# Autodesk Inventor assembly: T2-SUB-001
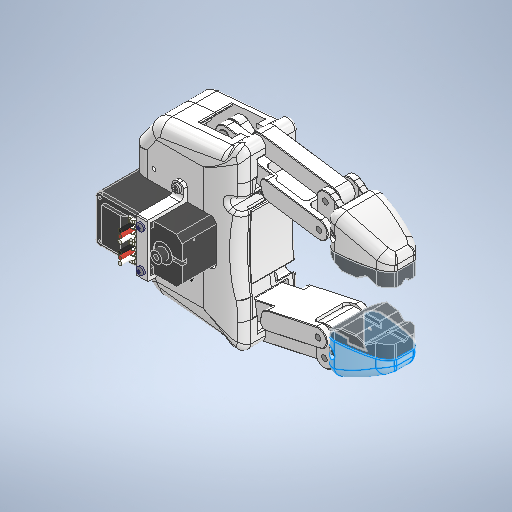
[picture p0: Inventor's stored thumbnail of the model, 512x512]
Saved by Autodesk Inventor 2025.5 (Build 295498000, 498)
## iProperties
Created: 2026-10
Part Number: T2-SUB-001
Document SubType Name: Assembly
Designer: Luis MuÃ±oz
Project: TESIS 2 - Plataforma mecatrÃ³nica preventiva desacoplada
Description: Gripper adaptativo instrumentado con puntas flexibles
Author: Luis M
Title: Gripper adaptativo instrumentado con puntas flexibles
Revision Number: 00
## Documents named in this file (22)
- C:\Users\Luis M\Desktop\TESIS\CAD_TESIS_PRUEBA_MIGRACION\GRIPPER_ADAPTATIVO_INSTRUMENTADO.iam
- C:\Users\Luis M\Desktop\TESIS\CAD_TESIS\PLACA_INFERIOR_GRIPPER.ipt
- C:\Users\Luis M\Desktop\TESIS\CAD_TESIS\ESLABON_INTERIOR.ipt
- C:\Users\Luis M\Desktop\TESIS\CAD_TESIS\ESLABON_EXTERIOR.ipt
- C:\Users\Luis M\Desktop\TESIS\CAD_TESIS\ESLABON_DISTAL.ipt
- C:\Users\Luis M\Desktop\TESIS\CAD_TESIS\CARCASA_DISTAL_DEDO.ipt
- C:\Users\Luis M\Desktop\TESIS\CAD_TESIS\SOPORTE_PUNTA_FLEXIBLE.ipt
- C:\Users\Luis M\Desktop\TESIS\CAD_TESIS\PUNTA_CONTACTO_REMOVIBLE.ipt
- C:\Users\Luis M\Desktop\TESIS\CAD_TESIS\PLACA_SUPERIOR_GRIPPER.ipt
- C:\Users\Luis M\Desktop\TESIS\CAD_TESIS\FEETECH_ST-3215-C018.iam
- C:\Users\Luis M\Desktop\TESIS\CAD_TESIS\ACOPLE_EJE_SERVOMOTOR.ipt
- C:\Users\Luis M\Desktop\TESIS\CAD_TESIS\LEVA_ACCIONAMIENTO.ipt
- C:\Users\Luis M\Desktop\TESIS\CAD_TESIS\BIELA_MOTRIZ.ipt
- C:\Users\Luis M\Desktop\TESIS\CAD_TESIS\MCM_99461A931_TORNILLO_M2_5X8.ipt
- C:\Users\Luis M\Desktop\TESIS\CAD_TESIS\INSERTO_ROSCADO_M3_D5_L5.ipt
- C:\Users\Luis M\Desktop\TESIS\CAD_TESIS\PASADOR_CILINDRICO_D3X16.ipt
- C:\Users\Luis M\Desktop\TESIS\CAD_TESIS\PASADOR_CILINDRICO_D3X24.ipt
- C:\Users\Luis M\Desktop\TESIS\CAD_TESIS\COJINETE_LISO_D3_D6_L5.ipt
- C:\Users\Luis M\Desktop\TESIS\CAD_TESIS\TORNILLO_HEX_INTERIOR_M3X10.ipt
- C:\Users\Luis M\Desktop\TESIS\CAD_TESIS\BRIDA_SERVOMOTOR.ipt
- C:\Users\Luis M\Desktop\TESIS\CAD_TESIS\TORNILLO_M2X4.ipt
- C:\Users\Luis M\Desktop\TESIS\CAD_TESIS\TORNILLO_HEX_INTERIOR_M3X6.ipt
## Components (70 placed, 21 different names)
1. PLACA_INFERIOR_GRIPPER:1
2. ESLABON_INTERIOR:1 — Coincidencia:1, Coincidencia:2, Coincidencia:12, Coincidencia:13, Coincidencia:49, Nivelación:13, Coincidencia:65, Coincidencia:66, Nivelación:15, Coincidencia:87, Coincidencia:92
3. ESLABON_INTERIOR:2 — Coincidencia:3, Coincidencia:4, Coincidencia:9, Coincidencia:14, Coincidencia:47, Nivelación:10, Coincidencia:63, Coincidencia:64, Nivelación:14, Coincidencia:89
4. ESLABON_EXTERIOR:1 — Coincidencia:6, Coincidencia:7, Coincidencia:11, Coincidencia:69
5. ESLABON_EXTERIOR:2 — Coincidencia:5, Coincidencia:8, Coincidencia:10, Coincidencia:70
6. ESLABON_DISTAL:1
7. ESLABON_DISTAL:2
8. Distal_Shell:2 — Coincidencia:15, Coincidencia:23, Nivelación:2, Nivelación:3, Coincidencia:71, Coincidencia:73, Coincidencia:74, Coincidencia:136
9. Distal_Shell:3 — Coincidencia:16, Coincidencia:24, Nivelación:1, Nivelación:4, Coincidencia:77, Coincidencia:78, Coincidencia:137
10. SOPORTE_PUNTA_FLEXIBLE:1 — Nivelación:3, Coincidencia:28, Coincidencia:136
11. SOPORTE_PUNTA_FLEXIBLE:2 — Coincidencia:29, Nivelación:4, Coincidencia:137
12. PUNTA_CONTACTO_REMOVIBLE:1 — Coincidencia:17, Coincidencia:18, Coincidencia:22, Coincidencia:23, Nivelación:2, Coincidencia:28, Coincidencia:57, Coincidencia:58, Coincidencia:59, Coincidencia:60, Coincidencia:61, Coincidencia:62, Coincidencia:72
13. PUNTA_CONTACTO_REMOVIBLE:2 — Coincidencia:19, Coincidencia:20, Coincidencia:21, Coincidencia:24, Nivelación:1, Coincidencia:29, Coincidencia:51, Coincidencia:52, Coincidencia:53, Coincidencia:54, Coincidencia:55, Coincidencia:56, Coincidencia:75, Coincidencia:76
14. PLACA_SUPERIOR_GRIPPER:1 — Coincidencia:25, Coincidencia:26, Coincidencia:27, Coincidencia:30, Coincidencia:31, Nivelación:5, Coincidencia:98, Coincidencia:99, Coincidencia:100, Coincidencia:102, Coincidencia:103, Coincidencia:104, Coincidencia:105, Coincidencia:106, Coincidencia:122, Coincidencia:123, Coincidencia:124, Coincidencia:126, Coincidencia:127, Coincidencia:130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
15. FEETECH_ST-3215-C018:1 [sub-assembly] — Coincidencia:30, Coincidencia:31, Nivelación:5, Coincidencia:35, Coincidencia:36, Coincidencia:135
16. ACOPLE_EJE:2 — Coincidencia:32, Coincidencia:33, Coincidencia:34, Coincidencia:36
17. Cam:1 — Coincidencia:32, Coincidencia:33, Coincidencia:34, Coincidencia:35, Coincidencia:45, Coincidencia:46, Nivelación:8, Nivelación:9, Coincidencia:112, Coincidencia:113, Coincidencia:114, Coincidencia:115, Coincidencia:116, Coincidencia:117, Coincidencia:118, Coincidencia:119, Coincidencia:120, Coincidencia:121, Coincidencia:135
18. BIELA_MOTRIZ:1 — Coincidencia:79, Coincidencia:80, Coincidencia:84, Nivelación:19, Coincidencia:85, Nivelación:21, Coincidencia:87
19. BIELA_MOTRIZ:2 — Coincidencia:81, Coincidencia:82, Coincidencia:83, Nivelación:18, Nivelación:20, Coincidencia:88, Coincidencia:89
20. MCM_99461A931_TORNILLO_M2_5X8:1 — Coincidencia:57, Coincidencia:61
21. INSERTO_ROSCADO_M3_D5_L5:1 — Coincidencia:85, Nivelación:21
22. PASADOR_CILINDRICO_D3X16:1 — Coincidencia:68, Nivelación:17
23. PASADOR_CILINDRICO_D3X24:1 — Coincidencia:65
24. COJINETE_LISO_D3_D6_L5:1 — Coincidencia:49, Nivelación:13, Coincidencia:79, Coincidencia:91
25. MCM_99461A931_TORNILLO_M2_5X8:2 — Coincidencia:101, Coincidencia:107
26. INSERTO_ROSCADO_M3_D5_L5:2 — Nivelación:20, Coincidencia:88
27. PASADOR_CILINDRICO_D3X16:2 — Coincidencia:69
28. PASADOR_CILINDRICO_D3X24:2 — Coincidencia:66, Nivelación:15
29. COJINETE_LISO_D3_D6_L5:2 — Coincidencia:83, Nivelación:18, Coincidencia:95, Coincidencia:96
30. MCM_99461A931_TORNILLO_M2_5X8:3 — Coincidencia:71, Coincidencia:73
31. INSERTO_ROSCADO_M3_D5_L5:3 — Coincidencia:45, Nivelación:9, Coincidencia:80
32. PASADOR_CILINDRICO_D3X16:3 — Coincidencia:67, Nivelación:16
33. PASADOR_CILINDRICO_D3X24:3 — Coincidencia:63
34. COJINETE_LISO_D3_D6_L5:3 — Coincidencia:47, Nivelación:10, Coincidencia:82, Coincidencia:90, Coincidencia:93
35. MCM_99461A931_TORNILLO_M2_5X8:4 — Coincidencia:72, Coincidencia:74
36. INSERTO_ROSCADO_M3_D5_L5:4 — Coincidencia:46, Nivelación:8, Coincidencia:81
37. PASADOR_CILINDRICO_D3X16:4 — Coincidencia:70
38. PASADOR_CILINDRICO_D3X24:4 — Coincidencia:64, Nivelación:14
39. COJINETE_LISO_D3_D6_L5:4 — Coincidencia:84, Nivelación:19, Coincidencia:94, Coincidencia:97
40. MCM_99461A931_TORNILLO_M2_5X8:5 — Coincidencia:102, Coincidencia:108
41. MCM_99461A931_TORNILLO_M2_5X8:6 — Coincidencia:104, Coincidencia:105
42. MCM_99461A931_TORNILLO_M2_5X8:7 — Coincidencia:75, Coincidencia:77
43. MCM_99461A931_TORNILLO_M2_5X8:8 — Coincidencia:76, Coincidencia:78
44. MCM_99461A931_TORNILLO_M2_5X8:10 — Coincidencia:125, Coincidencia:129
45. MCM_99461A931_TORNILLO_M2_5X8:11 — Coincidencia:122, Coincidencia:127
46. MCM_99461A931_TORNILLO_M2_5X8:12 — Coincidencia:123, Coincidencia:126
47. MCM_99461A931_TORNILLO_M2_5X8:13 — Coincidencia:51, Coincidencia:56
48. MCM_99461A931_TORNILLO_M2_5X8:14 — Coincidencia:58, Coincidencia:62
49. MCM_99461A931_TORNILLO_M2_5X8:16 — Coincidencia:124, Coincidencia:128
50. MCM_99461A931_TORNILLO_M2_5X8:17 — Coincidencia:52, Coincidencia:54
51. MCM_99461A931_TORNILLO_M2_5X8:18 — Coincidencia:53, Coincidencia:55
52. MCM_99461A931_TORNILLO_M2_5X8:19 — Coincidencia:59, Coincidencia:60
53. MCM_99461A931_TORNILLO_M2_5X8:20 — Coincidencia:103, Coincidencia:106
54. hex_socket_cylindrical_head_M3x10:1 — Coincidencia:90, Coincidencia:93
55. hex_socket_cylindrical_head_M3x10:2 — Coincidencia:91, Coincidencia:92
56. hex_socket_cylindrical_head_M3x10:3 — Coincidencia:94, Coincidencia:97
57. hex_socket_cylindrical_head_M3x10:4 — Coincidencia:95, Coincidencia:96
58. BRIDA_SERVOMOTOR:1
59. TORNILLO_M2X4:1 — Coincidencia:109, Nivelación:22
60. TORNILLO_M2X4:2 — Coincidencia:110, Nivelación:22, Coincidencia:111
61. TORNILLO_HEX_INTERIOR_M3X6:1 — Coincidencia:114, Coincidencia:120
62. TORNILLO_HEX_INTERIOR_M3X6:2 — Coincidencia:112, Coincidencia:113
63. TORNILLO_HEX_INTERIOR_M3X6:3 — Coincidencia:116, Coincidencia:119
64. TORNILLO_HEX_INTERIOR_M3X6:4 — Coincidencia:117, Coincidencia:118
65. TORNILLO_HEX_INTERIOR_M3X6:5 — Coincidencia:115, Coincidencia:121
66. INSERTO_ROSCADO_M3_D5_L5:9 — Coincidencia:131, Nivelación:27
67. INSERTO_ROSCADO_M3_D5_L5:10 — Coincidencia:130, Nivelación:23
68. INSERTO_ROSCADO_M3_D5_L5:11 — Coincidencia:134, Nivelación:26
69. INSERTO_ROSCADO_M3_D5_L5:12 — Coincidencia:132, Nivelación:24
70. INSERTO_ROSCADO_M3_D5_L5:13 — Coincidencia:133, Nivelación:25
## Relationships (149: Mate 126, Flush 23)
- Coincidencia:1 [Mate]: ESLABON_INTERIOR:1
- Coincidencia:2 [Mate]: ESLABON_INTERIOR:1
- Coincidencia:3 [Mate]: ESLABON_INTERIOR:2
- Coincidencia:4 [Mate]: ESLABON_INTERIOR:2
- Coincidencia:5 [Mate]: ESLABON_EXTERIOR:2
- Coincidencia:6 [Mate]: ESLABON_EXTERIOR:1
- Coincidencia:7 [Mate]: ESLABON_EXTERIOR:1
- Coincidencia:8 [Mate]: ESLABON_EXTERIOR:2
- Coincidencia:9 [Mate]: ESLABON_INTERIOR:2
- Coincidencia:10 [Mate]: ESLABON_EXTERIOR:2
- Coincidencia:11 [Mate]: ESLABON_EXTERIOR:1
- Coincidencia:12 [Mate]: ESLABON_INTERIOR:1
- Coincidencia:13 [Mate]: ESLABON_INTERIOR:1
- Coincidencia:14 [Mate]: ESLABON_INTERIOR:2
- Coincidencia:15 [Mate]: Distal_Shell:2
- Coincidencia:16 [Mate]: Distal_Shell:3
- Coincidencia:17 [Mate]: PUNTA_CONTACTO_REMOVIBLE:1
- Coincidencia:18 [Mate]: PUNTA_CONTACTO_REMOVIBLE:1
- Coincidencia:19 [Mate]: PUNTA_CONTACTO_REMOVIBLE:2
- Coincidencia:20 [Mate]: PUNTA_CONTACTO_REMOVIBLE:2
- Coincidencia:21 [Mate]: PUNTA_CONTACTO_REMOVIBLE:2
- Coincidencia:22 [Mate]: PUNTA_CONTACTO_REMOVIBLE:1
- Coincidencia:23 [Mate]: Distal_Shell:2 ↔ PUNTA_CONTACTO_REMOVIBLE:1
- Coincidencia:24 [Mate]: Distal_Shell:3 ↔ PUNTA_CONTACTO_REMOVIBLE:2
- Nivelación:1 [Flush]: Distal_Shell:3 ↔ PUNTA_CONTACTO_REMOVIBLE:2
- Nivelación:2 [Flush]: Distal_Shell:2 ↔ PUNTA_CONTACTO_REMOVIBLE:1
- Coincidencia:25 [Mate]: PLACA_SUPERIOR_GRIPPER:1
- Coincidencia:26 [Mate]: PLACA_SUPERIOR_GRIPPER:1
- Coincidencia:27 [Mate]: PLACA_SUPERIOR_GRIPPER:1
- Nivelación:3 [Flush]: Distal_Shell:2 ↔ SOPORTE_PUNTA_FLEXIBLE:1
- Coincidencia:28 [Mate]: SOPORTE_PUNTA_FLEXIBLE:1 ↔ PUNTA_CONTACTO_REMOVIBLE:1
- Coincidencia:29 [Mate]: SOPORTE_PUNTA_FLEXIBLE:2 ↔ PUNTA_CONTACTO_REMOVIBLE:2
- Nivelación:4 [Flush]: Distal_Shell:3 ↔ SOPORTE_PUNTA_FLEXIBLE:2
- Coincidencia:30 [Mate]: PLACA_SUPERIOR_GRIPPER:1 ↔ FEETECH_ST-3215-C018:1
- Coincidencia:31 [Mate]: PLACA_SUPERIOR_GRIPPER:1 ↔ FEETECH_ST-3215-C018:1
- Nivelación:5 [Flush]: PLACA_SUPERIOR_GRIPPER:1 ↔ FEETECH_ST-3215-C018:1
- Coincidencia:32 [Mate]: ACOPLE_EJE:2 ↔ Cam:1
- Coincidencia:33 [Mate]: ACOPLE_EJE:2 ↔ Cam:1
- Coincidencia:34 [Mate]: ACOPLE_EJE:2 ↔ Cam:1
- Coincidencia:35 [Mate]: FEETECH_ST-3215-C018:1 ↔ Cam:1
- Coincidencia:36 [Mate]: FEETECH_ST-3215-C018:1 ↔ ACOPLE_EJE:2
- Coincidencia:45 [Mate]: Cam:1 ↔ INSERTO_ROSCADO_M3_D5_L5:3
- Coincidencia:46 [Mate]: Cam:1 ↔ INSERTO_ROSCADO_M3_D5_L5:4
- Nivelación:8 [Flush]: Cam:1 ↔ INSERTO_ROSCADO_M3_D5_L5:4
- Nivelación:9 [Flush]: Cam:1 ↔ INSERTO_ROSCADO_M3_D5_L5:3
- Coincidencia:47 [Mate]: ESLABON_INTERIOR:2 ↔ COJINETE_LISO_D3_D6_L5:3
- Coincidencia:49 [Mate]: ESLABON_INTERIOR:1 ↔ COJINETE_LISO_D3_D6_L5:1
- Nivelación:10 [Flush]: ESLABON_INTERIOR:2 ↔ COJINETE_LISO_D3_D6_L5:3
- Nivelación:13 [Flush]: ESLABON_INTERIOR:1 ↔ COJINETE_LISO_D3_D6_L5:1
- Coincidencia:51 [Mate]: PUNTA_CONTACTO_REMOVIBLE:2 ↔ MCM_99461A931_TORNILLO_M2_5X8:13
- Coincidencia:52 [Mate]: PUNTA_CONTACTO_REMOVIBLE:2 ↔ MCM_99461A931_TORNILLO_M2_5X8:17
- Coincidencia:53 [Mate]: PUNTA_CONTACTO_REMOVIBLE:2 ↔ MCM_99461A931_TORNILLO_M2_5X8:18
- Coincidencia:54 [Mate]: PUNTA_CONTACTO_REMOVIBLE:2 ↔ MCM_99461A931_TORNILLO_M2_5X8:17
- Coincidencia:55 [Mate]: PUNTA_CONTACTO_REMOVIBLE:2 ↔ MCM_99461A931_TORNILLO_M2_5X8:18
- Coincidencia:56 [Mate]: PUNTA_CONTACTO_REMOVIBLE:2 ↔ MCM_99461A931_TORNILLO_M2_5X8:13
- Coincidencia:57 [Mate]: PUNTA_CONTACTO_REMOVIBLE:1 ↔ MCM_99461A931_TORNILLO_M2_5X8:1
- Coincidencia:58 [Mate]: PUNTA_CONTACTO_REMOVIBLE:1 ↔ MCM_99461A931_TORNILLO_M2_5X8:14
- Coincidencia:59 [Mate]: PUNTA_CONTACTO_REMOVIBLE:1 ↔ MCM_99461A931_TORNILLO_M2_5X8:19
- Coincidencia:60 [Mate]: PUNTA_CONTACTO_REMOVIBLE:1 ↔ MCM_99461A931_TORNILLO_M2_5X8:19
- Coincidencia:61 [Mate]: PUNTA_CONTACTO_REMOVIBLE:1 ↔ MCM_99461A931_TORNILLO_M2_5X8:1
- Coincidencia:62 [Mate]: PUNTA_CONTACTO_REMOVIBLE:1 ↔ MCM_99461A931_TORNILLO_M2_5X8:14
- Coincidencia:63 [Mate]: ESLABON_INTERIOR:2 ↔ PASADOR_CILINDRICO_D3X24:3
- Coincidencia:64 [Mate]: ESLABON_INTERIOR:2 ↔ PASADOR_CILINDRICO_D3X24:4
- Coincidencia:65 [Mate]: ESLABON_INTERIOR:1 ↔ PASADOR_CILINDRICO_D3X24:1
- Coincidencia:66 [Mate]: ESLABON_INTERIOR:1 ↔ PASADOR_CILINDRICO_D3X24:2
- Nivelación:14 [Flush]: ESLABON_INTERIOR:2 ↔ PASADOR_CILINDRICO_D3X24:4
- Nivelación:15 [Flush]: ESLABON_INTERIOR:1 ↔ PASADOR_CILINDRICO_D3X24:2
- Coincidencia:67 [Mate]: PASADOR_CILINDRICO_D3X16:3
- Coincidencia:68 [Mate]: PASADOR_CILINDRICO_D3X16:1
- Coincidencia:69 [Mate]: ESLABON_EXTERIOR:1 ↔ PASADOR_CILINDRICO_D3X16:2
- Coincidencia:70 [Mate]: ESLABON_EXTERIOR:2 ↔ PASADOR_CILINDRICO_D3X16:4
- Nivelación:16 [Flush]: PASADOR_CILINDRICO_D3X16:3
- Nivelación:17 [Flush]: PASADOR_CILINDRICO_D3X16:1
- Coincidencia:71 [Mate]: Distal_Shell:2 ↔ MCM_99461A931_TORNILLO_M2_5X8:3
- Coincidencia:72 [Mate]: PUNTA_CONTACTO_REMOVIBLE:1 ↔ MCM_99461A931_TORNILLO_M2_5X8:4
- Coincidencia:73 [Mate]: Distal_Shell:2 ↔ MCM_99461A931_TORNILLO_M2_5X8:3
- Coincidencia:74 [Mate]: Distal_Shell:2 ↔ MCM_99461A931_TORNILLO_M2_5X8:4
- Coincidencia:75 [Mate]: PUNTA_CONTACTO_REMOVIBLE:2 ↔ MCM_99461A931_TORNILLO_M2_5X8:7
- Coincidencia:76 [Mate]: PUNTA_CONTACTO_REMOVIBLE:2 ↔ MCM_99461A931_TORNILLO_M2_5X8:8
- Coincidencia:77 [Mate]: Distal_Shell:3 ↔ MCM_99461A931_TORNILLO_M2_5X8:7
- Coincidencia:78 [Mate]: Distal_Shell:3 ↔ MCM_99461A931_TORNILLO_M2_5X8:8
- Coincidencia:79 [Mate]: BIELA_MOTRIZ:1 ↔ COJINETE_LISO_D3_D6_L5:1
- Coincidencia:80 [Mate]: BIELA_MOTRIZ:1 ↔ INSERTO_ROSCADO_M3_D5_L5:3
- Coincidencia:81 [Mate]: BIELA_MOTRIZ:2 ↔ INSERTO_ROSCADO_M3_D5_L5:4
- Coincidencia:82 [Mate]: BIELA_MOTRIZ:2 ↔ COJINETE_LISO_D3_D6_L5:3
- Coincidencia:83 [Mate]: BIELA_MOTRIZ:2 ↔ COJINETE_LISO_D3_D6_L5:2
- Nivelación:18 [Flush]: BIELA_MOTRIZ:2 ↔ COJINETE_LISO_D3_D6_L5:2
- Coincidencia:84 [Mate]: BIELA_MOTRIZ:1 ↔ COJINETE_LISO_D3_D6_L5:4
- Nivelación:19 [Flush]: BIELA_MOTRIZ:1 ↔ COJINETE_LISO_D3_D6_L5:4
- Coincidencia:85 [Mate]: BIELA_MOTRIZ:1 ↔ INSERTO_ROSCADO_M3_D5_L5:1
- Nivelación:20 [Flush]: BIELA_MOTRIZ:2 ↔ INSERTO_ROSCADO_M3_D5_L5:2
- Nivelación:21 [Flush]: BIELA_MOTRIZ:1 ↔ INSERTO_ROSCADO_M3_D5_L5:1
- Coincidencia:87 [Mate]: ESLABON_INTERIOR:1 ↔ BIELA_MOTRIZ:1
- Coincidencia:88 [Mate]: BIELA_MOTRIZ:2 ↔ INSERTO_ROSCADO_M3_D5_L5:2
- Coincidencia:89 [Mate]: ESLABON_INTERIOR:2 ↔ BIELA_MOTRIZ:2
- Coincidencia:90 [Mate]: COJINETE_LISO_D3_D6_L5:3 ↔ hex_socket_cylindrical_head_M3x10:1
- Coincidencia:91 [Mate]: COJINETE_LISO_D3_D6_L5:1 ↔ hex_socket_cylindrical_head_M3x10:2
- Coincidencia:92 [Mate]: ESLABON_INTERIOR:1 ↔ hex_socket_cylindrical_head_M3x10:2
- Coincidencia:93 [Mate]: COJINETE_LISO_D3_D6_L5:3 ↔ hex_socket_cylindrical_head_M3x10:1
- Coincidencia:94 [Mate]: COJINETE_LISO_D3_D6_L5:4 ↔ hex_socket_cylindrical_head_M3x10:3
- Coincidencia:95 [Mate]: COJINETE_LISO_D3_D6_L5:2 ↔ hex_socket_cylindrical_head_M3x10:4
- Coincidencia:96 [Mate]: COJINETE_LISO_D3_D6_L5:2 ↔ hex_socket_cylindrical_head_M3x10:4
- Coincidencia:97 [Mate]: COJINETE_LISO_D3_D6_L5:4 ↔ hex_socket_cylindrical_head_M3x10:3
- Coincidencia:98 [Mate]: PLACA_SUPERIOR_GRIPPER:1
- Coincidencia:99 [Mate]: PLACA_SUPERIOR_GRIPPER:1
- Coincidencia:100 [Mate]: PLACA_SUPERIOR_GRIPPER:1
- Coincidencia:101 [Mate]: MCM_99461A931_TORNILLO_M2_5X8:2
- Coincidencia:102 [Mate]: PLACA_SUPERIOR_GRIPPER:1 ↔ MCM_99461A931_TORNILLO_M2_5X8:5
- Coincidencia:103 [Mate]: PLACA_SUPERIOR_GRIPPER:1 ↔ MCM_99461A931_TORNILLO_M2_5X8:20
- Coincidencia:104 [Mate]: PLACA_SUPERIOR_GRIPPER:1 ↔ MCM_99461A931_TORNILLO_M2_5X8:6
- Coincidencia:105 [Mate]: PLACA_SUPERIOR_GRIPPER:1 ↔ MCM_99461A931_TORNILLO_M2_5X8:6
- Coincidencia:106 [Mate]: PLACA_SUPERIOR_GRIPPER:1 ↔ MCM_99461A931_TORNILLO_M2_5X8:20
- Coincidencia:107 [Mate]: MCM_99461A931_TORNILLO_M2_5X8:2
- Coincidencia:108 [Mate]: MCM_99461A931_TORNILLO_M2_5X8:5
- Coincidencia:109 [Mate]: TORNILLO_M2X4:1
- Coincidencia:110 [Mate]: TORNILLO_M2X4:2
- Nivelación:22 [Flush]: TORNILLO_M2X4:1 ↔ TORNILLO_M2X4:2
- Coincidencia:111 [Mate]: TORNILLO_M2X4:2
- Coincidencia:112 [Mate]: Cam:1 ↔ TORNILLO_HEX_INTERIOR_M3X6:2
- Coincidencia:113 [Mate]: Cam:1 ↔ TORNILLO_HEX_INTERIOR_M3X6:2
- Coincidencia:114 [Mate]: Cam:1 ↔ TORNILLO_HEX_INTERIOR_M3X6:1
- Coincidencia:115 [Mate]: Cam:1 ↔ TORNILLO_HEX_INTERIOR_M3X6:5
- Coincidencia:116 [Mate]: Cam:1 ↔ TORNILLO_HEX_INTERIOR_M3X6:3
- Coincidencia:117 [Mate]: Cam:1 ↔ TORNILLO_HEX_INTERIOR_M3X6:4
- Coincidencia:118 [Mate]: Cam:1 ↔ TORNILLO_HEX_INTERIOR_M3X6:4
- Coincidencia:119 [Mate]: Cam:1 ↔ TORNILLO_HEX_INTERIOR_M3X6:3
- Coincidencia:120 [Mate]: Cam:1 ↔ TORNILLO_HEX_INTERIOR_M3X6:1
- Coincidencia:121 [Mate]: Cam:1 ↔ TORNILLO_HEX_INTERIOR_M3X6:5
- Coincidencia:122 [Mate]: PLACA_SUPERIOR_GRIPPER:1 ↔ MCM_99461A931_TORNILLO_M2_5X8:11
- Coincidencia:123 [Mate]: PLACA_SUPERIOR_GRIPPER:1 ↔ MCM_99461A931_TORNILLO_M2_5X8:12
- Coincidencia:124 [Mate]: PLACA_SUPERIOR_GRIPPER:1 ↔ MCM_99461A931_TORNILLO_M2_5X8:16
- Coincidencia:125 [Mate]: MCM_99461A931_TORNILLO_M2_5X8:10
- Coincidencia:126 [Mate]: PLACA_SUPERIOR_GRIPPER:1 ↔ MCM_99461A931_TORNILLO_M2_5X8:12
- Coincidencia:127 [Mate]: PLACA_SUPERIOR_GRIPPER:1 ↔ MCM_99461A931_TORNILLO_M2_5X8:11
- Coincidencia:128 [Mate]: MCM_99461A931_TORNILLO_M2_5X8:16
- Coincidencia:129 [Mate]: MCM_99461A931_TORNILLO_M2_5X8:10
- Coincidencia:130 [Mate]: PLACA_SUPERIOR_GRIPPER:1 ↔ INSERTO_ROSCADO_M3_D5_L5:10
- Coincidencia:131 [Mate]: PLACA_SUPERIOR_GRIPPER:1 ↔ INSERTO_ROSCADO_M3_D5_L5:9
- Coincidencia:132 [Mate]: INSERTO_ROSCADO_M3_D5_L5:12
- Coincidencia:133 [Mate]: INSERTO_ROSCADO_M3_D5_L5:13
- Coincidencia:134 [Mate]: INSERTO_ROSCADO_M3_D5_L5:11
- Nivelación:23 [Flush]: PLACA_SUPERIOR_GRIPPER:1 ↔ INSERTO_ROSCADO_M3_D5_L5:10
- Nivelación:24 [Flush]: INSERTO_ROSCADO_M3_D5_L5:12
- Nivelación:25 [Flush]: INSERTO_ROSCADO_M3_D5_L5:13
- Nivelación:26 [Flush]: INSERTO_ROSCADO_M3_D5_L5:11
- Nivelación:27 [Flush]: PLACA_SUPERIOR_GRIPPER:1 ↔ INSERTO_ROSCADO_M3_D5_L5:9
- Coincidencia:135 [Mate]: FEETECH_ST-3215-C018:1 ↔ Cam:1
- Coincidencia:136 [Mate]: Distal_Shell:2 ↔ SOPORTE_PUNTA_FLEXIBLE:1
- Coincidencia:137 [Mate]: Distal_Shell:3 ↔ SOPORTE_PUNTA_FLEXIBLE:2
